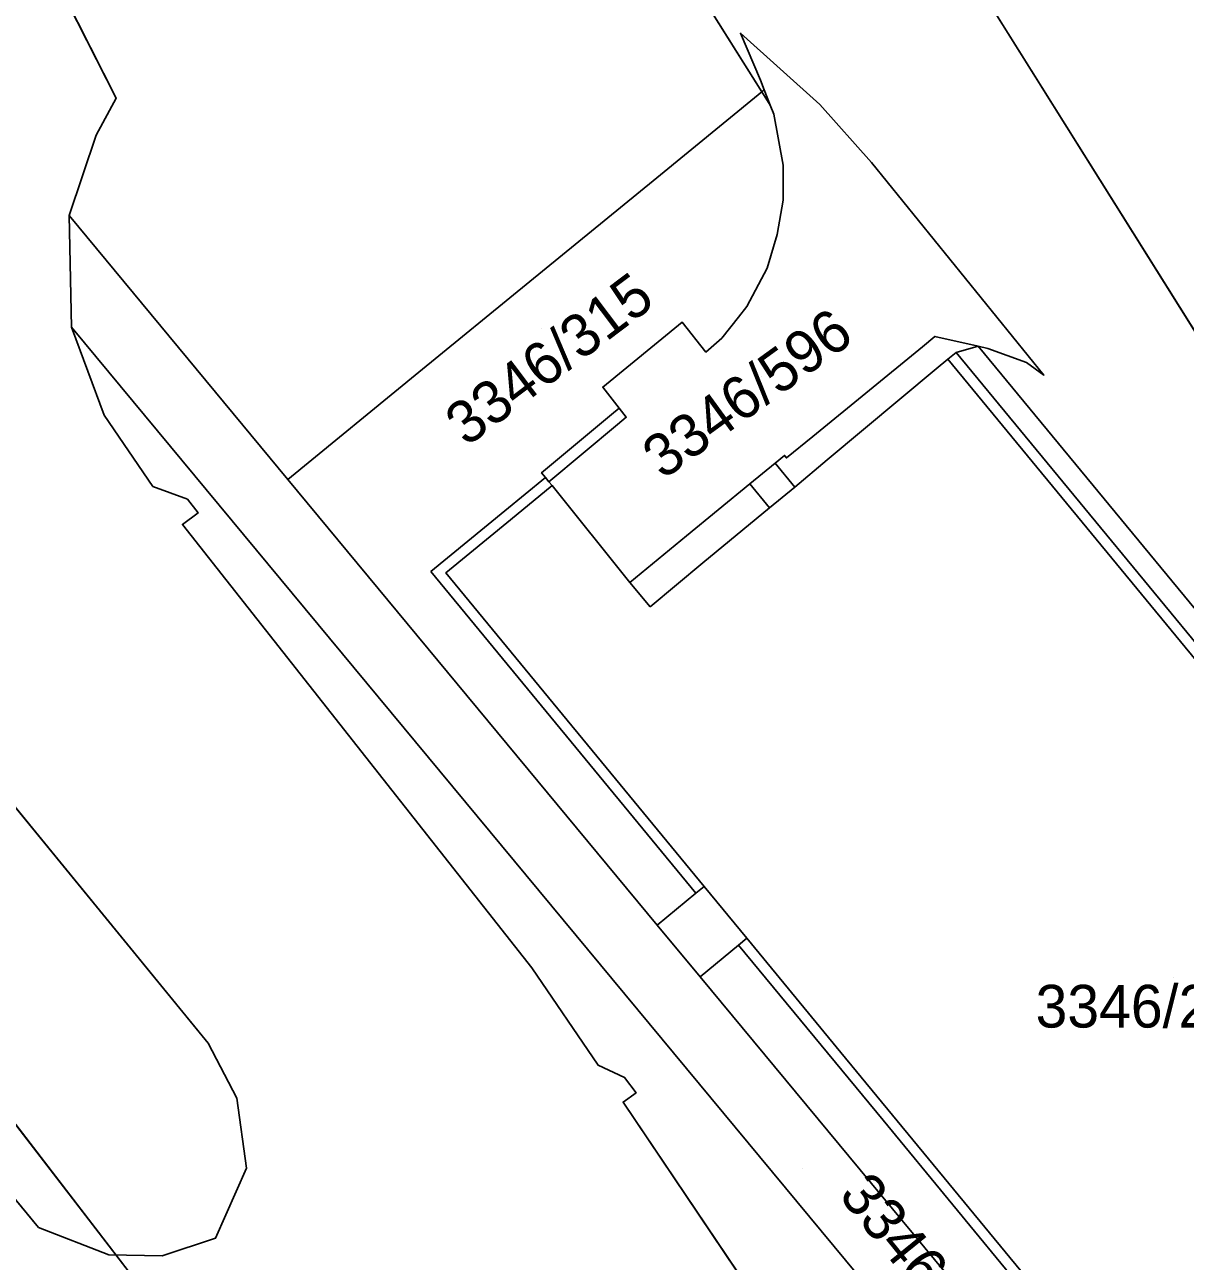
# Model space of a CAD drawing. Extents: x -262715 to -259381, y -1237238 to -1231182.
# Drawn here: x -262214.3 to -262159.9, y -1235517.9 to -1235460 of the extents above; entities that cross this region are included whole.
import ezdxf

# ---------------------------------------------------------------- set-up
doc = ezdxf.new("R2010")
doc.units = 0
for name, color, linetype in [('body_kn', 7, 'Continuous'), ('kladpar_druhypozemkov', 7, 'Continuous'), ('kladpar_hranice', 7, 'Continuous'), ('kladpar_parcelnecisla', 7, 'Continuous'), ('kladpar_plochy', 7, 'Continuous'), ('zappar_hrandruhpozemk', 7, 'Continuous')]:
    doc.layers.add(name, color=color, linetype=linetype)

msp = doc.modelspace()

# ---------------------------------------------------------------- linework, layer by layer
at = {"layer": 'body_kn'}
for p, q in [((-262180.75, -1235460.41), (-262180.75, -1235460.41)), ((-262179.8, -1235462.6), (-262179.8, -1235462.6)), ((-262179.74, -1235463.15), (-262179.74, -1235463.15)), ((-262179.74, -1235463.15), (-262179.74, -1235463.15)), ((-262179.63, -1235463.06), (-262179.63, -1235463.06)), ((-262179.63, -1235463.06), (-262179.63, -1235463.06)), ((-262209.97, -1235463.45), (-262209.97, -1235463.45)), ((-262179.35, -1235463.77), (-262179.35, -1235463.77)), ((-262177.03, -1235463.74), (-262177.03, -1235463.74)), ((-262179.18, -1235464.2), (-262179.18, -1235464.2)), ((-262210.91, -1235465.18), (-262210.91, -1235465.18)), ((-262178.74, -1235466.58), (-262178.74, -1235466.58)), ((-262174.61, -1235466.46), (-262174.61, -1235466.46)), ((-262184.83, -1235467.31), (-262184.83, -1235467.31)), ((-262178.75, -1235468.22), (-262178.75, -1235468.22)), ((-262212.18, -1235468.94), (-262212.18, -1235468.94)), ((-262179.03, -1235469.83), (-262179.03, -1235469.83)), ((-262179.49, -1235471.41), (-262179.49, -1235471.41)), ((-262190.6, -1235472.03), (-262190.6, -1235472.03)), ((-262180.45, -1235473.2), (-262180.45, -1235473.2)), ((-262212.07, -1235474.16), (-262212.07, -1235474.16)), ((-262212.07, -1235474.16), (-262212.07, -1235474.16)), ((-262183.48, -1235473.93), (-262183.48, -1235473.93)), ((-262180.84, -1235473.7), (-262180.84, -1235473.7)), ((-262181.62, -1235474.68), (-262181.62, -1235474.68)), ((-262171.64, -1235474.6), (-262171.64, -1235474.6)), ((-262182.36, -1235475.33), (-262182.36, -1235475.33)), ((-262172.23, -1235475.08), (-262172.23, -1235475.08)), ((-262170.65, -1235475.35), (-262170.65, -1235475.35)), ((-262170.65, -1235475.35), (-262170.65, -1235475.35)), ((-262169.62, -1235475.05), (-262169.62, -1235475.05)), ((-262169.16, -1235475.16), (-262169.16, -1235475.16)), ((-262171.04, -1235475.67), (-262171.04, -1235475.67)), ((-262171.04, -1235475.67), (-262171.04, -1235475.67)), ((-262167.35, -1235475.82), (-262167.35, -1235475.82)), ((-262195.8, -1235476.27), (-262195.8, -1235476.27)), ((-262171.58, -1235476.12), (-262171.58, -1235476.12)), ((-262166.54, -1235476.41), (-262166.54, -1235476.41)), ((-262187.19, -1235476.97), (-262187.19, -1235476.97)), ((-262210.54, -1235478.29), (-262210.54, -1235478.29)), ((-262186.79, -1235478.26), (-262186.79, -1235478.26)), ((-262186.42, -1235477.95), (-262186.42, -1235477.95)), ((-262186.42, -1235477.95), (-262186.42, -1235477.95)), ((-262186.5, -1235478.72), (-262186.5, -1235478.72)), ((-262186.5, -1235478.72), (-262186.5, -1235478.72)), ((-262186.09, -1235478.38), (-262186.09, -1235478.38)), ((-262177.36, -1235479.29), (-262177.36, -1235479.29)), ((-262179.12, -1235480.53), (-262179.12, -1235480.53)), ((-262179.12, -1235480.53), (-262179.12, -1235480.53)), ((-262178.68, -1235480.17), (-262178.68, -1235480.17)), ((-262178.59, -1235480.29), (-262178.59, -1235480.29)), ((-262176.68, -1235480.38), (-262176.68, -1235480.38)), ((-262190.06, -1235480.98), (-262190.06, -1235480.98)), ((-262208.25, -1235481.63), (-262208.25, -1235481.63)), ((-262201.93, -1235481.3), (-262201.93, -1235481.3)), ((-262201.93, -1235481.3), (-262201.93, -1235481.3)), ((-262189.88, -1235481.2), (-262189.88, -1235481.2)), ((-262189.72, -1235481.4), (-262189.72, -1235481.4)), ((-262189.56, -1235481.58), (-262189.56, -1235481.58)), ((-262180.3, -1235481.5), (-262180.3, -1235481.5)), ((-262178.2, -1235481.65), (-262178.2, -1235481.65)), ((-262206.64, -1235482.22), (-262206.64, -1235482.22)), ((-262206.14, -1235482.86), (-262206.14, -1235482.86)), ((-262191.78, -1235482.76), (-262191.78, -1235482.76)), ((-262191.78, -1235482.76), (-262191.78, -1235482.76)), ((-262179.38, -1235482.62), (-262179.38, -1235482.62)), ((-262179.38, -1235482.62), (-262179.38, -1235482.62)), ((-262206.87, -1235483.4), (-262206.87, -1235483.4)), ((-262191.51, -1235483.18), (-262191.51, -1235483.18)), ((-262183.27, -1235483.94), (-262183.27, -1235483.94)), ((-262182.5, -1235485.2), (-262182.5, -1235485.2)), ((-262182.5, -1235485.2), (-262182.5, -1235485.2)), ((-262195.24, -1235485.61), (-262195.24, -1235485.61)), ((-262194.54, -1235485.67), (-262194.54, -1235485.67)), ((-262194.54, -1235485.67), (-262194.54, -1235485.67)), ((-262185.92, -1235486.11), (-262185.92, -1235486.11)), ((-262185.92, -1235486.11), (-262185.92, -1235486.11)), ((-262184.98, -1235487.25), (-262184.98, -1235487.25)), ((-262182.83, -1235500.66), (-262182.83, -1235500.66)), ((-262182.45, -1235500.34), (-262182.45, -1235500.34)), ((-262182.45, -1235500.34), (-262182.45, -1235500.34)), ((-262184.64, -1235502.15), (-262184.64, -1235502.15)), ((-262184.64, -1235502.15), (-262184.64, -1235502.15)), ((-262180.83, -1235503.09), (-262180.83, -1235503.09)), ((-262180.83, -1235503.09), (-262180.83, -1235503.09)), ((-262180.44, -1235502.77), (-262180.44, -1235502.77)), ((-262180.44, -1235502.77), (-262180.44, -1235502.77)), ((-262190.52, -1235504.16), (-262190.52, -1235504.16)), ((-262182.63, -1235504.58), (-262182.63, -1235504.58)), ((-262205.66, -1235507.68), (-262205.66, -1235507.68)), ((-262176.04, -1235508.11), (-262176.04, -1235508.11)), ((-262187.41, -1235508.71), (-262187.41, -1235508.71)), ((-262186.17, -1235509.28), (-262186.17, -1235509.28)), ((-262185.63, -1235510), (-262185.63, -1235510)), ((-262204.32, -1235510.25), (-262204.32, -1235510.25)), ((-262186.24, -1235510.44), (-262186.24, -1235510.44)), ((-262174.07, -1235511.29), (-262174.07, -1235511.29)), ((-262174.07, -1235511.29), (-262174.07, -1235511.29)), ((-262203.87, -1235513.53), (-262203.87, -1235513.53)), ((-262213.61, -1235516.31), (-262213.61, -1235516.31)), ((-262205.32, -1235516.81), (-262205.32, -1235516.81)), ((-262210.32, -1235517.58), (-262210.32, -1235517.58)), ((-262207.82, -1235517.63), (-262207.82, -1235517.63))]:
    msp.add_line(p, q, dxfattribs=at)
at = {"layer": 'kladpar_druhypozemkov'}
for p, q in [((-262190.06, -1235474.21), (-262190.06, -1235474.21)), ((-262179.76, -1235476.47), (-262179.76, -1235476.47)), ((-262160.48, -1235504.59), (-262160.48, -1235504.59)), ((-262177.84, -1235513.54), (-262177.84, -1235513.54))]:
    msp.add_line(p, q, dxfattribs=at)
at = {"layer": 'kladpar_hranice'}
for p, q in [((-262100.82, -1235659.07), (-262455.78, -1235199.04)), ((-262455.78, -1235199.04), (-262100.82, -1235659.07))]:
    msp.add_line(p, q, dxfattribs=at)
for points in [[(-262389.58, -1235302.98), (-262390.13, -1235298.71), (-262387.33, -1235293.79), (-262383.12, -1235292.1), (-262377.12, -1235294.6), (-262306.16, -1235380.65), (-262271.88, -1235422.49), (-262262.62, -1235433.79), (-262251.23, -1235447.69), (-262234.08, -1235472.95), (-262205.66, -1235507.68), (-262204.32, -1235510.25), (-262203.87, -1235513.53), (-262205.32, -1235516.81), (-262207.82, -1235517.63), (-262210.32, -1235517.58), (-262213.61, -1235516.31), (-262255.74, -1235465.27), (-262274, -1235443.14), (-262283.24, -1235431.94), (-262334.59, -1235369.71), (-262389.58, -1235302.98)], [(-262377.12, -1235294.6), (-262383.12, -1235292.1), (-262387.33, -1235293.79), (-262390.13, -1235298.71), (-262389.58, -1235302.98), (-262334.59, -1235369.71), (-262283.24, -1235431.94), (-262274, -1235443.14), (-262255.74, -1235465.27), (-262213.61, -1235516.31), (-262210.32, -1235517.58), (-262207.82, -1235517.63), (-262205.32, -1235516.81), (-262203.87, -1235513.53), (-262204.32, -1235510.25), (-262205.66, -1235507.68), (-262234.08, -1235472.95), (-262251.23, -1235447.69), (-262262.62, -1235433.79), (-262271.88, -1235422.49), (-262306.16, -1235380.65), (-262377.12, -1235294.6)], [(-262179.74, -1235463.15), (-262229.53, -1235384.07), (-262220.74, -1235376.62), (-262151.79, -1235486.61), (-262139.99, -1235505.41), (-262136.39, -1235511.14), (-262125.06, -1235529.19), (-262127.88, -1235525.76), (-262144.61, -1235505.4), (-262153.03, -1235495.15), (-262169.62, -1235475.05), (-262169.16, -1235475.16), (-262167.35, -1235475.82), (-262166.54, -1235476.41), (-262174.61, -1235466.46), (-262177.03, -1235463.74), (-262180.75, -1235460.41), (-262179.8, -1235462.6), (-262179.63, -1235463.06), (-262179.74, -1235463.15)], [(-262151.79, -1235486.61), (-262220.74, -1235376.62)], [(-262229.53, -1235384.07), (-262179.74, -1235463.15), (-262184.83, -1235467.31), (-262190.6, -1235472.03), (-262195.8, -1235476.27), (-262201.93, -1235481.3), (-262212.18, -1235468.94), (-262210.91, -1235465.18), (-262209.97, -1235463.45), (-262214.09, -1235455.33)], [(-262214.09, -1235455.33), (-262209.97, -1235463.45), (-262210.91, -1235465.18), (-262212.18, -1235468.94), (-262212.07, -1235474.16), (-262210.54, -1235478.29), (-262208.25, -1235481.63), (-262206.64, -1235482.22), (-262206.14, -1235482.86), (-262206.87, -1235483.4), (-262190.52, -1235504.16), (-262187.41, -1235508.71), (-262186.17, -1235509.28), (-262185.63, -1235510), (-262186.24, -1235510.44), (-262172.11, -1235531.39), (-262166.85, -1235537.77), (-262165.56, -1235538.04), (-262164.94, -1235538.75), (-262165.58, -1235539.32), (-262133.43, -1235578.19)], [(-262179.74, -1235463.15), (-262179.63, -1235463.06), (-262179.8, -1235462.6), (-262180.75, -1235460.41), (-262177.03, -1235463.74), (-262174.61, -1235466.46), (-262166.54, -1235476.41), (-262167.35, -1235475.82), (-262169.16, -1235475.16), (-262169.62, -1235475.05), (-262170.65, -1235475.35), (-262171.04, -1235475.67), (-262171.58, -1235476.12), (-262176.68, -1235480.38), (-262178.2, -1235481.65), (-262179.12, -1235480.53), (-262180.3, -1235481.5), (-262183.27, -1235483.94), (-262185.92, -1235486.11), (-262189.56, -1235481.58), (-262189.72, -1235481.4), (-262189.88, -1235481.2), (-262190.06, -1235480.98), (-262186.79, -1235478.26), (-262186.42, -1235477.95), (-262187.19, -1235476.97), (-262183.48, -1235473.93), (-262182.36, -1235475.33), (-262181.62, -1235474.68), (-262180.84, -1235473.7), (-262180.45, -1235473.2), (-262179.49, -1235471.41), (-262179.03, -1235469.83), (-262178.75, -1235468.22), (-262178.74, -1235466.58), (-262179.18, -1235464.2), (-262179.35, -1235463.77), (-262179.74, -1235463.15)], [(-262201.93, -1235481.3), (-262195.8, -1235476.27), (-262190.6, -1235472.03), (-262184.83, -1235467.31), (-262179.74, -1235463.15), (-262179.35, -1235463.77), (-262179.18, -1235464.2), (-262178.74, -1235466.58), (-262178.75, -1235468.22), (-262179.03, -1235469.83), (-262179.49, -1235471.41), (-262180.45, -1235473.2), (-262180.84, -1235473.7), (-262181.62, -1235474.68), (-262182.36, -1235475.33), (-262183.48, -1235473.93), (-262187.19, -1235476.97), (-262186.42, -1235477.95), (-262186.79, -1235478.26), (-262190.06, -1235480.98), (-262189.88, -1235481.2), (-262189.72, -1235481.4), (-262189.56, -1235481.58), (-262191.51, -1235483.18), (-262194.54, -1235485.67), (-262182.45, -1235500.34), (-262180.44, -1235502.77), (-262176.04, -1235508.11), (-262147.91, -1235542.24)], [(-262212.07, -1235474.16), (-262212.18, -1235468.94), (-262201.93, -1235481.3), (-262184.64, -1235502.15), (-262182.63, -1235504.58), (-262165.16, -1235525.65), (-262146.94, -1235547.63), (-262145.68, -1235549.15), (-262143.96, -1235551.22), (-262146.43, -1235553.27), (-262212.07, -1235474.16)], [(-262133.43, -1235578.19), (-262165.58, -1235539.32), (-262164.94, -1235538.75), (-262165.56, -1235538.04), (-262166.85, -1235537.77), (-262172.11, -1235531.39), (-262186.24, -1235510.44), (-262185.63, -1235510), (-262186.17, -1235509.28), (-262187.41, -1235508.71), (-262190.52, -1235504.16), (-262206.87, -1235483.4), (-262206.14, -1235482.86), (-262206.64, -1235482.22), (-262208.25, -1235481.63), (-262210.54, -1235478.29), (-262212.07, -1235474.16), (-262146.43, -1235553.27)], [(-262171.04, -1235475.67), (-262170.65, -1235475.35), (-262169.62, -1235475.05), (-262153.03, -1235495.15), (-262144.61, -1235505.4), (-262127.88, -1235525.76), (-262128.6, -1235526.35), (-262128.99, -1235526.67), (-262171.04, -1235475.67)], [(-262194.54, -1235485.67), (-262191.51, -1235483.18), (-262189.56, -1235481.58), (-262185.92, -1235486.11), (-262183.27, -1235483.94), (-262180.3, -1235481.5), (-262179.12, -1235480.53), (-262178.2, -1235481.65), (-262176.68, -1235480.38), (-262171.58, -1235476.12), (-262171.04, -1235475.67), (-262128.99, -1235526.67)], [(-262146.94, -1235547.63), (-262165.16, -1235525.65), (-262182.63, -1235504.58), (-262184.64, -1235502.15), (-262201.93, -1235481.3)], [(-262147.91, -1235542.24), (-262176.04, -1235508.11), (-262180.44, -1235502.77), (-262182.45, -1235500.34), (-262194.54, -1235485.67)]]:
    msp.add_lwpolyline(points, dxfattribs=at)
at = {"layer": 'kladpar_plochy'}
for p, q in [((-262151.79, -1235486.61), (-262220.74, -1235376.62)), ((-262229.53, -1235384.07), (-262179.74, -1235463.15)), ((-262214.09, -1235455.33), (-262209.97, -1235463.45)), ((-262209.97, -1235463.45), (-262214.09, -1235455.33)), ((-262179.74, -1235463.15), (-262184.83, -1235467.31)), ((-262209.97, -1235463.45), (-262210.91, -1235465.18)), ((-262210.91, -1235465.18), (-262209.97, -1235463.45)), ((-262255.74, -1235465.27), (-262213.61, -1235516.31)), ((-262210.91, -1235465.18), (-262212.18, -1235468.94)), ((-262212.18, -1235468.94), (-262210.91, -1235465.18)), ((-262184.83, -1235467.31), (-262190.6, -1235472.03)), ((-262212.18, -1235468.94), (-262212.07, -1235474.16)), ((-262201.93, -1235481.3), (-262212.18, -1235468.94)), ((-262190.6, -1235472.03), (-262195.8, -1235476.27)), ((-262205.66, -1235507.68), (-262234.08, -1235472.95)), ((-262212.07, -1235474.16), (-262210.54, -1235478.29)), ((-262195.8, -1235476.27), (-262201.93, -1235481.3)), ((-262210.54, -1235478.29), (-262208.25, -1235481.63)), ((-262208.25, -1235481.63), (-262206.64, -1235482.22)), ((-262206.64, -1235482.22), (-262206.14, -1235482.86)), ((-262206.14, -1235482.86), (-262206.87, -1235483.4)), ((-262206.87, -1235483.4), (-262190.52, -1235504.16)), ((-262190.52, -1235504.16), (-262187.41, -1235508.71)), ((-262204.32, -1235510.25), (-262205.66, -1235507.68)), ((-262187.41, -1235508.71), (-262186.17, -1235509.28)), ((-262186.17, -1235509.28), (-262185.63, -1235510)), ((-262185.63, -1235510), (-262186.24, -1235510.44)), ((-262203.87, -1235513.53), (-262204.32, -1235510.25)), ((-262186.24, -1235510.44), (-262172.11, -1235531.39)), ((-262205.32, -1235516.81), (-262203.87, -1235513.53)), ((-262213.61, -1235516.31), (-262210.32, -1235517.58)), ((-262207.82, -1235517.63), (-262205.32, -1235516.81)), ((-262210.32, -1235517.58), (-262207.82, -1235517.63))]:
    msp.add_line(p, q, dxfattribs=at)
for points in [[(-262389.58, -1235302.98), (-262390.13, -1235298.71), (-262387.33, -1235293.79), (-262383.12, -1235292.1), (-262377.12, -1235294.6), (-262306.16, -1235380.65), (-262271.88, -1235422.49), (-262262.62, -1235433.79), (-262251.23, -1235447.69), (-262234.08, -1235472.95), (-262205.66, -1235507.68), (-262204.32, -1235510.25), (-262203.87, -1235513.53), (-262205.32, -1235516.81), (-262207.82, -1235517.63), (-262210.32, -1235517.58), (-262213.61, -1235516.31), (-262255.74, -1235465.27), (-262274, -1235443.14), (-262283.24, -1235431.94), (-262334.59, -1235369.71)], [(-262179.74, -1235463.15), (-262229.53, -1235384.07), (-262220.74, -1235376.62), (-262151.79, -1235486.61), (-262139.99, -1235505.41), (-262136.39, -1235511.14), (-262125.06, -1235529.19), (-262127.88, -1235525.76), (-262144.61, -1235505.4), (-262153.03, -1235495.15), (-262169.62, -1235475.05), (-262169.16, -1235475.16), (-262167.35, -1235475.82), (-262166.54, -1235476.41), (-262174.61, -1235466.46), (-262177.03, -1235463.74), (-262180.75, -1235460.41), (-262179.8, -1235462.6), (-262179.63, -1235463.06)], [(-262179.74, -1235463.15), (-262179.63, -1235463.06), (-262179.8, -1235462.6), (-262180.75, -1235460.41), (-262177.03, -1235463.74), (-262174.61, -1235466.46), (-262166.54, -1235476.41), (-262167.35, -1235475.82), (-262169.16, -1235475.16), (-262169.62, -1235475.05), (-262170.65, -1235475.35), (-262171.04, -1235475.67), (-262171.58, -1235476.12), (-262176.68, -1235480.38), (-262178.2, -1235481.65), (-262179.12, -1235480.53), (-262180.3, -1235481.5), (-262183.27, -1235483.94), (-262185.92, -1235486.11), (-262189.56, -1235481.58), (-262189.72, -1235481.4), (-262189.88, -1235481.2), (-262190.06, -1235480.98), (-262186.79, -1235478.26), (-262186.42, -1235477.95), (-262187.19, -1235476.97), (-262183.48, -1235473.93), (-262182.36, -1235475.33), (-262181.62, -1235474.68), (-262180.84, -1235473.7), (-262180.45, -1235473.2), (-262179.49, -1235471.41), (-262179.03, -1235469.83), (-262178.75, -1235468.22), (-262178.74, -1235466.58), (-262179.18, -1235464.2), (-262179.35, -1235463.77)], [(-262212.07, -1235474.16), (-262212.18, -1235468.94), (-262201.93, -1235481.3), (-262184.64, -1235502.15), (-262182.63, -1235504.58), (-262165.16, -1235525.65), (-262146.94, -1235547.63), (-262145.68, -1235549.15), (-262143.96, -1235551.22), (-262146.43, -1235553.27)], [(-262171.04, -1235475.67), (-262170.65, -1235475.35), (-262169.62, -1235475.05), (-262153.03, -1235495.15), (-262144.61, -1235505.4), (-262127.88, -1235525.76), (-262128.6, -1235526.35), (-262128.99, -1235526.67)], [(-262194.54, -1235485.67), (-262191.51, -1235483.18), (-262189.56, -1235481.58), (-262185.92, -1235486.11), (-262183.27, -1235483.94), (-262180.3, -1235481.5), (-262179.12, -1235480.53), (-262178.2, -1235481.65), (-262176.68, -1235480.38), (-262171.58, -1235476.12), (-262171.04, -1235475.67), (-262128.99, -1235526.67), (-262135.95, -1235532.4), (-262133.84, -1235534.97), (-262134.26, -1235535.33), (-262136.87, -1235537.52), (-262139.01, -1235534.92), (-262141.47, -1235536.95), (-262142.24, -1235537.58), (-262147.46, -1235541.87), (-262147.91, -1235542.24), (-262176.04, -1235508.11), (-262180.44, -1235502.77), (-262182.45, -1235500.34)]]:
    msp.add_lwpolyline(points, close=True, dxfattribs=at)
for points in [[(-262165.16, -1235525.65), (-262182.63, -1235504.58), (-262184.64, -1235502.15), (-262201.93, -1235481.3), (-262195.8, -1235476.27), (-262190.6, -1235472.03), (-262184.83, -1235467.31), (-262179.74, -1235463.15), (-262179.35, -1235463.77), (-262179.18, -1235464.2), (-262178.74, -1235466.58), (-262178.75, -1235468.22), (-262179.03, -1235469.83), (-262179.49, -1235471.41), (-262180.45, -1235473.2), (-262180.84, -1235473.7), (-262181.62, -1235474.68), (-262182.36, -1235475.33), (-262183.48, -1235473.93), (-262187.19, -1235476.97), (-262186.42, -1235477.95), (-262186.79, -1235478.26), (-262190.06, -1235480.98), (-262189.88, -1235481.2), (-262189.72, -1235481.4), (-262189.56, -1235481.58), (-262191.51, -1235483.18), (-262194.54, -1235485.67), (-262182.45, -1235500.34), (-262180.44, -1235502.77), (-262176.04, -1235508.11), (-262147.91, -1235542.24)], [(-262133.43, -1235578.19), (-262165.58, -1235539.32), (-262164.94, -1235538.75), (-262165.56, -1235538.04), (-262166.85, -1235537.77), (-262172.11, -1235531.39), (-262186.24, -1235510.44), (-262185.63, -1235510), (-262186.17, -1235509.28), (-262187.41, -1235508.71), (-262190.52, -1235504.16), (-262206.87, -1235483.4), (-262206.14, -1235482.86), (-262206.64, -1235482.22), (-262208.25, -1235481.63), (-262210.54, -1235478.29), (-262212.07, -1235474.16), (-262146.43, -1235553.27)]]:
    msp.add_lwpolyline(points, dxfattribs=at)
at = {"layer": 'zappar_hrandruhpozemk'}
for p, q in [((-262179.63, -1235463.06), (-262179.35, -1235463.77)), ((-262172.23, -1235475.08), (-262177.36, -1235479.29)), ((-262170.65, -1235475.35), (-262128.6, -1235526.35)), ((-262186.5, -1235478.72), (-262189.72, -1235481.4)), ((-262191.78, -1235482.76), (-262189.88, -1235481.2)), ((-262179.38, -1235482.62), (-262178.2, -1235481.65)), ((-262195.24, -1235485.61), (-262191.78, -1235482.76)), ((-262184.98, -1235487.25), (-262182.5, -1235485.2)), ((-262185.92, -1235486.11), (-262184.98, -1235487.25)), ((-262182.45, -1235500.34), (-262182.83, -1235500.66)), ((-262180.83, -1235503.09), (-262182.63, -1235504.58)), ((-262180.44, -1235502.77), (-262180.83, -1235503.09)), ((-262174.07, -1235511.29), (-262180.83, -1235503.09)), ((-262155.34, -1235534.01), (-262174.07, -1235511.29))]:
    msp.add_line(p, q, dxfattribs=at)
for points in [[(-262172.23, -1235475.08), (-262171.64, -1235474.6), (-262169.62, -1235475.05)], [(-262186.42, -1235477.95), (-262186.09, -1235478.38), (-262186.5, -1235478.72)], [(-262179.12, -1235480.53), (-262178.68, -1235480.17), (-262178.59, -1235480.29), (-262177.36, -1235479.29)], [(-262182.5, -1235485.2), (-262179.38, -1235482.62), (-262180.3, -1235481.5)], [(-262184.64, -1235502.15), (-262182.83, -1235500.66), (-262195.24, -1235485.61)]]:
    msp.add_lwpolyline(points, dxfattribs=at)

# ---------------------------------------------------------------- texts
at = {"layer": 'kladpar_parcelnecisla'}
for s, rotation, p in [('3346/315', 37, (-262193.569, -1235479.795)), ('3346/596', 36, (-262184.368, -1235481.336)), ('3346/566', 309, (-262176.194, -1235514.808))]:
    msp.add_text(s, height=2, rotation=rotation, dxfattribs=at).set_placement(p)
msp.add_text('3346/277', height=2, dxfattribs=at).set_placement((-262166.929, -1235506.95))

doc.saveas('drawing.dxf')
